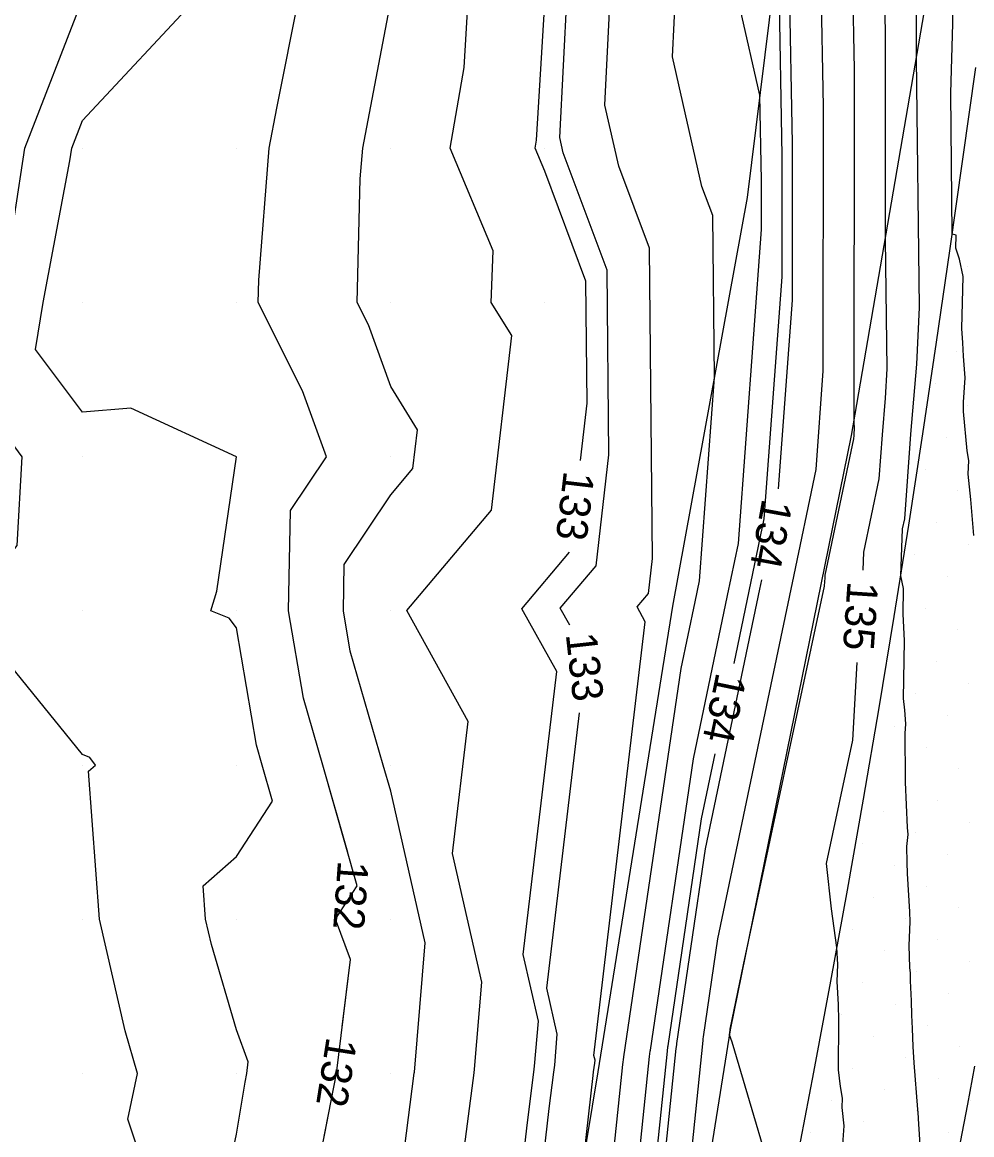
# Model space of a CAD drawing. Extents: x 2354170 to 2357230, y 866100 to 868290.
# Drawn here: x 2355256.1 to 2355317.7, y 866576 to 866648.2 of the extents above; entities that cross this region are included whole.
import ezdxf

# ---------------------------------------------------------------- set-up
doc = ezdxf.new("R2010")
doc.units = 0
for name, color, linetype in [('Default', 7, 'Continuous'), ('DTM Contours Major', 7, 'Continuous'), ('DTM Contours Major Text', 7, 'Continuous'), ('DTM Contours Minor', 7, 'Continuous'), ('DTM Contours Minor Text', 7, 'Continuous'), ('Exist DTM Breakline', 7, 'Continuous'), ('Exist DTM QL2 LIDAR Elevation Point', 7, 'Continuous'), ('Exist DTM Scan Elevation Point', 7, 'Continuous'), ('Exist Roads EOP', 7, 'Continuous'), ('PH Exist DTM Breakline', 7, 'Continuous')]:
    doc.layers.add(name, color=color, linetype=linetype)

msp = doc.modelspace()

# ---------------------------------------------------------------- linework, layer by layer
at = {"layer": 'Default'}
for points in [[(2355297.254, 866553.133), (2355300.242, 866582.149), (2355300.258, 866582.264), (2355300.271, 866582.388), (2355301.207, 866588.733), (2355306.039, 866611.833), (2355307.575, 866619.179), (2355308.045, 866625.572), (2355308.05, 866642.705), (2355307.912, 866650.725), (2355306.883, 866663.997), (2355306.877, 866664.275), (2355309.469, 866674.543), (2355309.616, 866676.566), (2355311.337, 866691.623), (2355311.395, 866694.073), (2355311.306, 866696.992), (2355311.955, 866723.587)], [(2355294.327, 866573.741), (2355295.033, 866580.597), (2355295.1, 866581.054), (2355295.103, 866581.083), (2355298.818, 866606.265), (2355299.722, 866610.589), (2355300.01, 866611.964), (2355300.976, 866625.132), (2355300.871, 866635.655), (2355300.17, 866637.53), (2355298.262, 866645.936), (2355298.486, 866650.364), (2355298.284, 866654.76), (2355296.563, 866661.7), (2355297.356, 866667.489), (2355298.837, 866672.669), (2355299.392, 866677.825), (2355301.044, 866686.872), (2355302.64, 866691.421), (2355302.675, 866693.277), (2355302.697, 866696.84), (2355303.653, 866704.38), (2355303.877, 866715.546), (2355303.438, 866721.661)], [(2355295.303, 866566.872), (2355296.769, 866581.115), (2355296.82, 866581.457), (2355296.826, 866581.518), (2355299.614, 866600.421), (2355301.828, 866611.003), (2355302.532, 866614.369), (2355304.026, 866634.729), (2355304.027, 866637.909), (2355303.932, 866643.444), (2355302.653, 866649.078), (2355302.727, 866650.543), (2355302.661, 866651.997), (2355300.033, 866662.592), (2355300.554, 866666.398), (2355302.677, 866673.822), (2355303.017, 866676.986), (2355305.307, 866689.515), (2355306.111, 866691.809), (2355306.156, 866694.173), (2355306.167, 866695.977), (2355306.651, 866699.793), (2355307.057, 866720.06)], [(2355292.29, 866619.765), (2355292.722, 866623.479), (2355292.643, 866631.389), (2355289.975, 866638.525), (2355289.353, 866640.006), (2355289.445, 866640.536), (2355289.975, 866649.424), (2355290.004, 866650.008), (2355289.975, 866650.65), (2355289.707, 866660.007), (2355289.975, 866662.483), (2355290.959, 866669.671), (2355291.156, 866670.362), (2355292.14, 866679.505), (2355292.52, 866681.586), (2355295.699, 866690.646), (2355295.715, 866691.485), (2355295.758, 866698.568), (2355296.806, 866706.839), (2355297.066, 866710.007), (2355296.559, 866716.591), (2355295.979, 866718.165)], [(2355305.137, 866617.912), (2355306.035, 866630.151), (2355306.038, 866640.307), (2355305.861, 866650.662), (2355305.487, 866655.484), (2355303.503, 866663.485), (2355303.753, 866665.307), (2355306.517, 866674.976), (2355306.643, 866676.146), (2355309.569, 866692.159), (2355309.582, 866692.197), (2355309.636, 866695.069), (2355309.637, 866695.113), (2355309.648, 866695.206), (2355310.084, 866716.937)], [(2355310.632, 866612.647), (2355310.679, 866613.818), (2355311.675, 866618.572), (2355311.886, 866621.43), (2355312.081, 866623.792), (2355312.179, 866625.695), (2355312.069, 866634.113), (2355312.073, 866647.502), (2355312.015, 866650.85), (2355311.586, 866656.391), (2355311.431, 866663.538), (2355312.853, 866669.171), (2355313.707, 866680.984), (2355314.788, 866690.445), (2355314.825, 866691.984), (2355314.552, 866700.892), (2355314.828, 866712.227)], [(2355317.815, 866614.891), (2355317.626, 866617.221), (2355317.45, 866618.87), (2355317.477, 866619.757), (2355317.38, 866620.382), (2355317.14, 866622.932), (2355317.14, 866623.538), (2355317.249, 866625.123), (2355317.142, 866626.534), (2355317.09, 866627.387), (2355317.039, 866628.327), (2355317.113, 866631.688), (2355316.881, 866632.815), (2355316.633, 866633.528), (2355316.659, 866634.375), (2355316.41, 866634.427), (2355316.316, 866643.571), (2355316.438, 866648.107), (2355316.459, 866651.039), (2355316.233, 866652.654), (2355316.097, 866657.591), (2355315.984, 866662.802), (2355316.236, 866663.8), (2355317.798, 866685.403)], [(2355277.191, 866594.328), (2355275.565, 866600.006), (2355274.309, 866604.34), (2355273.349, 866610.006), (2355273.47, 866616.511), (2355275.801, 866620.006), (2355274.249, 866624.281), (2355271.381, 866630.006), (2355271.418, 866631.45), (2355272.087, 866640.006), (2355272.584, 866642.616), (2355274.05, 866650.006), (2355272.585, 866657.396), (2355279.975, 866655.894), (2355281.844, 866658.137), (2355281.791, 866660.007), (2355282.01, 866662.042), (2355282.186, 866670.007), (2355279.975, 866675.894), (2355274.433, 866677.575)], [(2355292.529, 866574.719), (2355293.113, 866579.886), (2355293.143, 866580.115), (2355293.215, 866580.667), (2355293.232, 866580.874), (2355293.163, 866581.18), (2355296.492, 866609.303), (2355295.957, 866610.265), (2355296.693, 866611.137), (2355296.958, 866613.414), (2355296.757, 866633.522), (2355294.768, 866638.842), (2355293.871, 866642.794), (2355294.245, 866650.186)], [(2355305.573, 866570.413), (2355302.127, 866582.037), (2355301.962, 866582.517), (2355301.978, 866582.667), (2355301.978, 866582.667), (2355301.994, 866582.823), (2355302.004, 866582.889), (2355302.874, 866587.051), (2355308.127, 866611.602), (2355308.144, 866611.917), (2355308.162, 866612.139), (2355308.169, 866612.315), (2355310.024, 866621.162), (2355310.04, 866621.385), (2355310.055, 866621.569), (2355310.063, 866621.717), (2355310.054, 866622.374), (2355310.061, 866645.104), (2355309.964, 866650.787)], [(2355265.25, 866570.006), (2355262.926, 866577.054), (2355263.554, 866580.006), (2355262.738, 866582.77), (2355261.083, 866590.006), (2355260.374, 866599.606), (2355260.827, 866600.006), (2355260.46, 866600.492), (2355259.974, 866600.683), (2355252.415, 866610.006), (2355255.736, 866614.244), (2355256.074, 866620.006), (2355253.463, 866623.495), (2355254.509, 866630.006), (2355255.565, 866635.597), (2355256.228, 866640.006), (2355259.974, 866649.668)], [(2355268.91, 866571.07), (2355269.974, 866576.08), (2355270.535, 866579.445), (2355270.644, 866580.006), (2355270.737, 866580.768), (2355269.974, 866582.835), (2355268.341, 866588.372), (2355267.967, 866590.006), (2355267.807, 866592.173), (2355269.974, 866594.082), (2355272.306, 866597.675), (2355271.638, 866600.006), (2355271.264, 866601.296), (2355269.974, 866608.913), (2355269.504, 866609.536), (2355268.308, 866610.006), (2355268.702, 866611.278), (2355269.971, 866620.006), (2355263.111, 866623.143), (2355259.974, 866622.898), (2355256.932, 866626.964), (2355257.42, 866630.006), (2355259.155, 866639.187), (2355259.278, 866640.006), (2355259.974, 866641.801), (2355267.615, 866650.006)], [(2355280.24, 866570.205), (2355281.509, 866580.018), (2355281.518, 866580.083), (2355282.203, 866588.471), (2355279.975, 866598.317), (2355279.491, 866600.006), (2355277.354, 866607.385), (2355276.91, 866610.006), (2355276.965, 866613.015), (2355279.975, 866617.527), (2355281.42, 866619.24), (2355281.71, 866621.742), (2355279.975, 866624.563), (2355278.525, 866628.557), (2355277.799, 866630.006), (2355278.004, 866638.036), (2355278.158, 866640.006), (2355279.975, 866649.542)], [(2355284.531, 866573.432), (2355285.387, 866580.051), (2355285.417, 866580.277), (2355285.879, 866585.939), (2355283.994, 866594.268), (2355285.009, 866602.839), (2355281.014, 866610.023), (2355286.511, 866616.539), (2355287.825, 866627.857), (2355286.503, 866630.006), (2355286.634, 866633.347), (2355283.839, 866640.006), (2355284.744, 866645.237), (2355285.028, 866650.006)], [(2355314.395, 866574.394), (2355314.218, 866577.063), (2355314.196, 866577.523), (2355314.185, 866577.588), (2355314.175, 866577.673), (2355313.94, 866580.69), (2355313.882, 866581.76), (2355313.833, 866582.934), (2355313.796, 866583.784), (2355313.775, 866584.726), (2355313.699, 866586.015), (2355313.693, 866586.514), (2355313.651, 866586.877), (2355313.618, 866588.302), (2355313.689, 866589.849), (2355313.661, 866590.489), (2355313.511, 866592.965), (2355313.478, 866593.686), (2355313.466, 866594.725), (2355313.542, 866595.503), (2355313.507, 866595.965), (2355313.378, 866598.904), (2355313.374, 866599.051), (2355313.373, 866599.077), (2355313.369, 866599.11), (2355313.35, 866602.064), (2355313.392, 866602.689), (2355313.324, 866603.571), (2355313.245, 866604.325), (2355313.308, 866608.073), (2355313.307, 866608.096), (2355313.233, 866609.792), (2355313.256, 866611.462), (2355313.066, 866612.278), (2355313.188, 866615.322), (2355313.326, 866615.982), (2355313.731, 866621.475), (2355314.107, 866626.014), (2355314.294, 866629.672), (2355314.083, 866645.852), (2355314.084, 866649.9)], [(2355278.1, 866517.733), (2355278.153, 866519.189), (2355283.314, 866540.931), (2355282.469, 866543.114), (2355283.083, 866545.791), (2355283.38, 866550.377), (2355285.134, 866552.254), (2355286.41, 866555.344), (2355288.822, 866576.659), (2355289.265, 866580.083), (2355289.316, 866580.472), (2355289.556, 866583.406), (2355288.578, 866587.724), (2355290.751, 866606.071), (2355288.485, 866610.144), (2355291.58, 866613.812)], [(2355287.735, 866513.992), (2355289.944, 866521.071), (2355295.198, 866537.511), (2355295.282, 866537.938), (2355295.372, 866538.337), (2355295.459, 866538.711), (2355295.54, 866539.076), (2355295.622, 866539.415), (2355295.699, 866539.75), (2355295.775, 866540.077), (2355295.845, 866540.398), (2355295.913, 866540.712), (2355295.982, 866541.023), (2355295.717, 866543.597), (2355295.224, 866552.454), (2355296.278, 866560.002), (2355298.505, 866581.632), (2355298.539, 866581.861), (2355298.549, 866581.953), (2355300.411, 866594.577), (2355303.933, 866611.418), (2355304.059, 866612.018)], [(2355309.262, 866574.792), (2355309.394, 866576.618), (2355309.261, 866577.791), (2355309.292, 866578.401), (2355309.163, 866579.159), (2355309.033, 866580.25), (2355309.059, 866583.434), (2355309.023, 866584.472), (2355308.935, 866585.974), (2355308.98, 866587.079), (2355308.931, 866588.174), (2355308.582, 866590.674), (2355308.243, 866593.634), (2355309.952, 866601.621), (2355310.231, 866606.661)], [(2355275.405, 866574.575), (2355276.46, 866580.006), (2355277.365, 866587.396), (2355276.808, 866588.903)]]:
    msp.add_lwpolyline(points, dxfattribs=at)
at = {"layer": 'DTM Contours Major'}
for points in [[(2355310.632, 866612.647), (2355310.679, 866613.818), (2355311.675, 866618.572), (2355311.886, 866621.43), (2355312.081, 866623.792), (2355312.179, 866625.695), (2355312.069, 866634.113), (2355312.073, 866647.502), (2355312.015, 866650.85), (2355311.586, 866656.391), (2355311.431, 866663.538), (2355312.853, 866669.171), (2355313.707, 866680.984), (2355314.788, 866690.445), (2355314.825, 866691.984), (2355314.552, 866700.892), (2355314.828, 866712.227)], [(2355309.262, 866574.792), (2355309.394, 866576.618), (2355309.261, 866577.791), (2355309.292, 866578.401), (2355309.163, 866579.159), (2355309.033, 866580.25), (2355309.059, 866583.434), (2355309.023, 866584.472), (2355308.935, 866585.974), (2355308.98, 866587.079), (2355308.931, 866588.174), (2355308.582, 866590.674), (2355308.243, 866593.634), (2355309.952, 866601.621), (2355310.231, 866606.661)]]:
    msp.add_lwpolyline(points, dxfattribs=at)
at = {"layer": 'DTM Contours Minor'}
for points in [[(2355302.253, 866606.603), (2355303.231, 866611.28), (2355304.213, 866615.972), (2355305.365, 866631.677), (2355305.368, 866639.508), (2355305.177, 866650.642), (2355305.05, 866652.286), (2355302.346, 866663.187), (2355302.687, 866665.671), (2355305.237, 866674.592), (2355305.434, 866676.426), (2355308.148, 866691.278), (2355308.425, 866692.067), (2355308.476, 866694.77), (2355308.48, 866695.401), (2355308.649, 866696.735), (2355309.177, 866723.07)], [(2355291.588, 866609.084), (2355290.976, 866610.184), (2355293.299, 866612.938), (2355294.134, 866620.124), (2355294.014, 866632.1), (2355291.166, 866639.717), (2355290.943, 866640.699), (2355291.418, 866650.067), (2355290.99, 866659.365), (2355290.78, 866660.214), (2355292.025, 866669.307), (2355292.436, 866670.746), (2355293.349, 866679.225), (2355293.941, 866682.467), (2355296.856, 866690.775), (2355296.875, 866691.783), (2355296.915, 866698.28), (2355298.172, 866708.205), (2355298.32, 866710.007), (2355297.723, 866717.756), (2355296.893, 866720.007)], [(2355276.831, 866583.035), (2355277.365, 866587.396), (2355276.402, 866590.006), (2355277.808, 866592.173), (2355275.565, 866600.006), (2355274.309, 866604.34), (2355273.349, 866610.006), (2355273.47, 866616.511), (2355275.801, 866620.006), (2355274.249, 866624.281), (2355271.381, 866630.006), (2355271.418, 866631.45), (2355272.087, 866640.006), (2355272.584, 866642.616), (2355274.05, 866650.006)], [(2355287.45, 866552.974), (2355290.253, 866577.735), (2355290.558, 866580.093), (2355290.616, 866580.537), (2355290.781, 866582.562), (2355290.107, 866585.543), (2355292.219, 866603.389)], [(2355295.953, 866562.292), (2355297.927, 866581.46), (2355297.966, 866581.726), (2355297.974, 866581.808), (2355300.145, 866596.525), (2355301.025, 866600.73)], [(2355275.405, 866574.575), (2355275.898, 866577.112)]]:
    msp.add_lwpolyline(points, dxfattribs=at)
at = {"layer": 'Exist DTM Breakline'}
msp.add_lwpolyline([(2355316.955, 866575.558), (2355317.426, 866578.013), (2355317.881, 866580.472)], dxfattribs=at)
at = {"layer": 'Exist DTM QL2 LIDAR Elevation Point'}
for p, q in [((2355259.974, 866640.006), (2355259.974, 866640.006)), ((2355269.974, 866640.006), (2355269.974, 866640.006)), ((2355279.975, 866640.006), (2355279.975, 866640.006)), ((2355289.975, 866640.006), (2355289.975, 866640.006)), ((2355259.974, 866630.006), (2355259.974, 866630.006)), ((2355269.974, 866630.006), (2355269.974, 866630.006)), ((2355279.975, 866630.006), (2355279.975, 866630.006)), ((2355289.975, 866630.006), (2355289.975, 866630.006)), ((2355259.974, 866620.006), (2355259.974, 866620.006)), ((2355269.974, 866620.006), (2355269.974, 866620.006)), ((2355279.975, 866620.006), (2355279.975, 866620.006)), ((2355259.974, 866610.006), (2355259.974, 866610.006)), ((2355269.974, 866610.006), (2355269.974, 866610.006)), ((2355279.975, 866610.006), (2355279.975, 866610.006)), ((2355259.974, 866600.006), (2355259.974, 866600.006)), ((2355269.974, 866600.006), (2355269.974, 866600.006)), ((2355279.975, 866600.006), (2355279.975, 866600.006)), ((2355259.974, 866590.006), (2355259.974, 866590.006)), ((2355269.974, 866590.006), (2355269.974, 866590.006)), ((2355279.975, 866590.006), (2355279.975, 866590.006)), ((2355259.974, 866580.006), (2355259.974, 866580.006)), ((2355269.974, 866580.006), (2355269.974, 866580.006)), ((2355279.975, 866580.006), (2355279.975, 866580.006))]:
    msp.add_line(p, q, dxfattribs=at)
at = {"layer": 'Exist DTM Scan Elevation Point'}
for p, q in [((2355317.387, 866632.367), (2355317.387, 866632.367)), ((2355316.713, 866626.818), (2355316.713, 866626.818)), ((2355315.334, 866624.733), (2355315.334, 866624.733)), ((2355317.419, 866623.353), (2355317.419, 866623.353)), ((2355316.039, 866621.268), (2355316.039, 866621.268)), ((2355314.66, 866619.183), (2355314.66, 866619.183)), ((2355316.745, 866617.804), (2355316.745, 866617.804)), ((2355315.365, 866615.719), (2355315.365, 866615.719)), ((2355317.45, 866614.34), (2355317.45, 866614.34)), ((2355313.986, 866613.634), (2355313.986, 866613.634)), ((2355316.071, 866612.255), (2355316.071, 866612.255)), ((2355314.691, 866610.17), (2355314.691, 866610.17)), ((2355316.776, 866608.79), (2355316.776, 866608.79)), ((2355313.312, 866608.085), (2355313.312, 866608.085)), ((2355315.397, 866606.705), (2355315.397, 866606.705)), ((2355317.482, 866605.326), (2355317.482, 866605.326)), ((2355314.018, 866604.62), (2355314.018, 866604.62)), ((2355316.103, 866603.241), (2355316.103, 866603.241)), ((2355312.638, 866602.535), (2355312.638, 866602.535)), ((2355314.723, 866601.156), (2355314.723, 866601.156)), ((2355316.808, 866599.776), (2355316.808, 866599.776)), ((2355313.344, 866599.071), (2355313.344, 866599.071)), ((2355315.429, 866597.691), (2355315.429, 866597.691)), ((2355311.964, 866596.986), (2355311.964, 866596.986)), ((2355317.514, 866596.312), (2355317.514, 866596.312)), ((2355314.049, 866595.606), (2355314.049, 866595.606)), ((2355310.585, 866594.901), (2355310.585, 866594.901)), ((2355316.134, 866594.227), (2355316.134, 866594.227)), ((2355312.67, 866593.521), (2355312.67, 866593.521)), ((2355314.755, 866592.142), (2355314.755, 866592.142)), ((2355311.29, 866591.436), (2355311.29, 866591.436)), ((2355316.84, 866590.763), (2355316.84, 866590.763)), ((2355313.375, 866590.057), (2355313.375, 866590.057)), ((2355309.911, 866589.351), (2355309.911, 866589.351)), ((2355315.46, 866588.678), (2355315.46, 866588.678)), ((2355311.996, 866587.972), (2355311.996, 866587.972)), ((2355317.545, 866587.298), (2355317.545, 866587.298)), ((2355314.081, 866586.593), (2355314.081, 866586.593)), ((2355310.617, 866585.887), (2355310.617, 866585.887)), ((2355316.166, 866585.213), (2355316.166, 866585.213)), ((2355312.702, 866584.508), (2355312.702, 866584.508)), ((2355309.237, 866583.802), (2355309.237, 866583.802)), ((2355314.787, 866583.128), (2355314.787, 866583.128)), ((2355311.322, 866582.423), (2355311.322, 866582.423)), ((2355316.872, 866581.749), (2355316.872, 866581.749)), ((2355313.407, 866581.043), (2355313.407, 866581.043)), ((2355309.943, 866580.338), (2355309.943, 866580.338)), ((2355315.492, 866579.664), (2355315.492, 866579.664)), ((2355312.028, 866578.958), (2355312.028, 866578.958)), ((2355308.563, 866578.253), (2355308.563, 866578.253)), ((2355317.577, 866578.284), (2355317.577, 866578.284)), ((2355314.113, 866577.579), (2355314.113, 866577.579)), ((2355310.648, 866576.873), (2355310.648, 866576.873)), ((2355307.184, 866576.168), (2355307.184, 866576.168)), ((2355316.198, 866576.199), (2355316.198, 866576.199))]:
    msp.add_line(p, q, dxfattribs=at)
at = {"layer": 'Exist Roads EOP'}
msp.add_lwpolyline([(2355306.315, 866574.202), (2355307.439, 866580.096), (2355308.536, 866585.994), (2355309.606, 866591.898), (2355310.649, 866597.807), (2355311.663, 866603.721), (2355312.644, 866609.64), (2355313.592, 866615.564), (2355314.508, 866621.494), (2355315.395, 866627.428), (2355316.259, 866633.366), (2355317.104, 866639.306), (2355317.935, 866645.248)], dxfattribs=at)
at = {"layer": 'PH Exist DTM Breakline'}
for points in [[(2355312.051, 866755.45), (2355310.592, 866725.079), (2355309.64, 866692.203), (2355308.77, 866675.653), (2355306.693, 866664.305), (2355304.823, 866650.631), (2355303.11, 866636.816), (2355298.268, 866610.302), (2355293.421, 866580.117), (2355287.51, 866544.368), (2355280.975, 866513.436), (2355273.382, 866486.505), (2355262.843, 866454.968), (2355248.318, 866418.016), (2355229.845, 866373.376), (2355221.154, 866356.908)], [(2355207.55, 866297.674), (2355225.072, 866335.019), (2355245.676, 866379.995), (2355260.219, 866424.767), (2355273.655, 866466.636), (2355281.785, 866490.339), (2355287.686, 866512.788), (2355295.16, 866540.197), (2355297.267, 866553.045), (2355302.012, 866582.828), (2355309.884, 866621.381), (2355316.964, 866662.644), (2355320.622, 866688.452), (2355323.199, 866711.282), (2355324.906, 866739.018), (2355325.362, 866751.624)]]:
    msp.add_lwpolyline(points, dxfattribs=at)

# ---------------------------------------------------------------- texts
at = {"layer": 'Default'}
for s, rotation, p in [('133', 263.19901, (2355291.217, 866619.131)), ('134', 259.63261, (2355304.093, 866617.342)), ('135', 266.17328, (2355309.617, 866611.958)), ('132', 265.96994, (2355276.555, 866593.846))]:
    msp.add_text(s, height=2, rotation=rotation, dxfattribs=at).set_placement(p)
at = {"layer": 'DTM Contours Major Text'}
msp.add_text('135', height=2, rotation=266.17328, dxfattribs=at).set_placement((2355309.617, 866611.958))
at = {"layer": 'DTM Contours Minor Text'}
for s, rotation, p in [('133', 276.32594, (2355291.331, 866608.488)), ('134', 258.18607, (2355301.119, 866606.068)), ('132', 261.05149, (2355275.828, 866582.43))]:
    msp.add_text(s, height=2, rotation=rotation, dxfattribs=at).set_placement(p)

doc.saveas('drawing.dxf')
